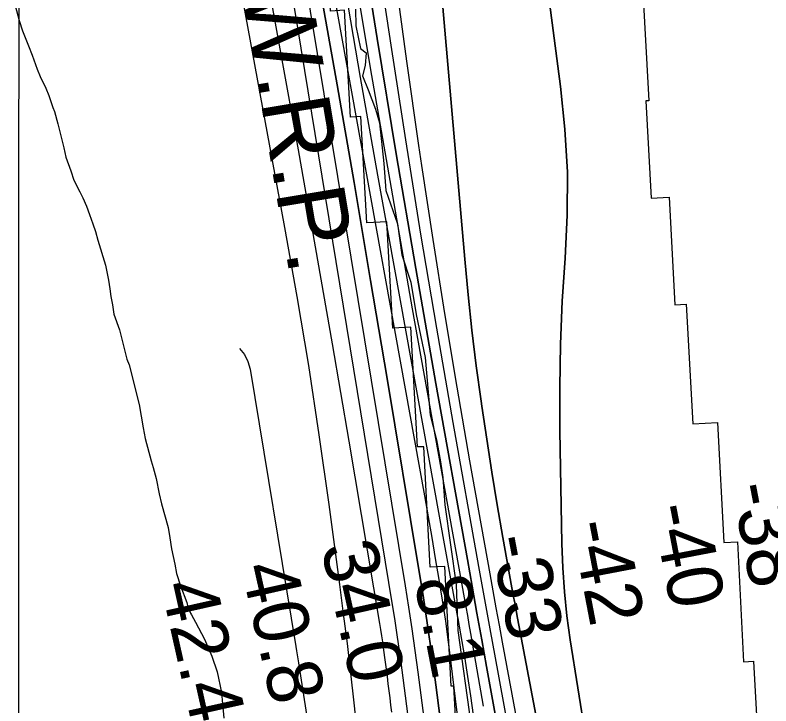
# Model space of a CAD drawing. Extents: x 3263578 to 3301413, y 764927 to 798602.
# Drawn here: x 3275589 to 3276507, y 791406 to 792245 of the extents above; entities that cross this region are included whole.
import ezdxf

# ---------------------------------------------------------------- set-up
doc = ezdxf.new("R2010")
doc.units = 0
for name, color, linetype in [('V-GRID-MAJR', 7, 'Continuous'), ('V-RIVR-EDGE', 7, 'Continuous'), ('V-RIVR-RANG', 7, 'Continuous'), ('V-RRAP-RVMT', 7, 'Continuous'), ('V-SITE-VEGE', 7, 'Continuous'), ('V-TOPO-DPTH', 7, 'Continuous'), ('V-TOPO-MAJR', 7, 'Continuous'), ('V-TOPO-MINR', 7, 'Continuous'), ('V-TOPO-WATR', 7, 'Continuous'), ('V-TOPO-WATR-IDEN', 7, 'Continuous')]:
    doc.layers.add(name, color=color, linetype=linetype)

msp = doc.modelspace()

# ---------------------------------------------------------------- linework, layer by layer
at = {"layer": 'V-GRID-MAJR'}
msp.add_spline([(3275591.3, 775830.01), (3275592.19, 781889.43), (3275593.07, 787951.47), (3275593.95, 794013.53), (3275593.95, 794016.1)], degree=3, dxfattribs=at)
at = {"layer": 'V-RIVR-EDGE'}
msp.add_lwpolyline([(3276002.53, 792252.02), (3276002.91, 792231.59), (3276008.49, 792204.19), (3276015.44, 792198.96), (3276014.09, 792183.74), (3276011.02, 792171.15), (3276017.93, 792154.18), (3276026.57, 792130.68), (3276031.31, 792114.15), (3276036.84, 792064.59), (3276039.36, 792031.98), (3276053.17, 791991.52), (3276058.73, 791953.69), (3276069.52, 791920.63), (3276075.94, 791881.06), (3276087.11, 791828.87), (3276093.02, 791758.87), (3276100.77, 791728.86), (3276105.49, 791702.33), (3276108.49, 791683.2), (3276111.01, 791650.15), (3276124.68, 791552.75), (3276126.72, 791497.54), (3276142.52, 791384.05)], dxfattribs=at)
at = {"layer": 'V-RRAP-RVMT'}
for points in [[(3276267.24, 792666.6), (3276274.68, 792537.22), (3276298.41, 792538.57), (3276305.94, 792408.68), (3276322.98, 792409.51), (3276330.56, 792279.44), (3276350.63, 792280.61), (3276358.29, 792140.86), (3276354.91, 792140.71), (3276361.31, 792022.46), (3276383.18, 792023.54), (3276389.99, 791893.13), (3276403.81, 791893.89), (3276411.76, 791748.26), (3276441.88, 791749.86), (3276449.37, 791604.37), (3276466.05, 791605.25), (3276473.51, 791459.54), (3276485.65, 791460.18), (3276493.76, 791314.12)], [(3276129.93, 791283.92), (3276121.78, 791429.9), (3276118.49, 791429.76), (3276110.85, 791575.36), (3276092.94, 791574.4), (3276085.31, 791720.67), (3276077.63, 791720.33), (3276069.68, 791865.87), (3276047.54, 791864.64), (3276040.6, 791993.84), (3276015.97, 791992.49), (3276008.76, 792121.61), (3275996.23, 792121.03), (3275988.92, 792250.72), (3275972.19, 792249.74), (3275964.1, 792388.74), (3275967.37, 792388.96), (3275964.86, 792431.92)]]:
    msp.add_lwpolyline(points, dxfattribs=at)
at = {"layer": 'V-SITE-VEGE'}
for p, q in [((3275589.1, 792256.42), (3275593.94, 792238.22)), ((3275593.94, 792238.22), (3275598.21, 792225.67)), ((3275598.21, 792225.67), (3275605.55, 792207.45)), ((3275605.55, 792207.45), (3275609.83, 792196.14)), ((3275609.83, 792196.14), (3275615.93, 792179.18)), ((3275615.93, 792179.18), (3275619.6, 792170.39)), ((3275619.6, 792170.39), (3275626.35, 792155.93)), ((3275626.35, 792155.93), (3275630.03, 792147.13)), ((3275630.03, 792147.13), (3275634.9, 792132.69)), ((3275634.9, 792132.69), (3275636.73, 792127.66)), ((3275636.73, 792127.66), (3275640.97, 792112.6)), ((3275640.97, 792112.6), (3275648.21, 792083.74)), ((3275648.21, 792083.74), (3275650.61, 792072.45)), ((3275650.61, 792072.45), (3275656.71, 792055.5)), ((3275656.71, 792055.5), (3275660.37, 792044.2)), ((3275660.37, 792044.2), (3275667.75, 792030.36)), ((3275667.75, 792030.36), (3275671.43, 792022.81)), ((3275671.43, 792022.81), (3275675.72, 792012.76)), ((3275675.72, 792012.76), (3275679.39, 792002.71)), ((3275679.39, 792002.71), (3275683.66, 791991.4)), ((3275683.66, 791991.4), (3275686.7, 791981.98)), ((3275686.7, 791981.98), (3275689.73, 791971.32)), ((3275689.73, 791971.32), (3275698.84, 791941.19)), ((3275698.84, 791941.19), (3275702.43, 791923)), ((3275702.43, 791923), (3275704.21, 791912.34)), ((3275704.21, 791912.34), (3275705.37, 791902.94)), ((3275705.37, 791902.94), (3275707.16, 791892.91)), ((3275707.16, 791892.91), (3275708.93, 791881.63)), ((3275708.93, 791881.63), (3275715.64, 791862.79)), ((3275715.64, 791862.79), (3275724.7, 791827.03)), ((3275724.7, 791827.03), (3275727.76, 791820.11)), ((3275727.76, 791820.11), (3275739.83, 791771.81)), ((3275739.83, 791771.81), (3275744.58, 791743.6)), ((3275744.58, 791743.6), (3275746.96, 791730.43)), ((3275746.96, 791730.43), (3275754.22, 791703.45)), ((3275754.22, 791703.45), (3275756.65, 791695.29)), ((3275756.65, 791695.29), (3275760.28, 791682.11)), ((3275760.28, 791682.11), (3275763.86, 791663.3)), ((3275763.86, 791663.3), (3275766.88, 791651.38)), ((3275766.88, 791651.38), (3275774.75, 791622.51)), ((3275774.75, 791622.51), (3275777.14, 791609.97)), ((3275777.14, 791609.97), (3275778.89, 791596.81)), ((3275778.89, 791596.81), (3275783.1, 791577.99)), ((3275783.1, 791577.99), (3275784.87, 791566.71)), ((3275784.87, 791566.71), (3275789.74, 791551.64)), ((3275789.74, 791551.64), (3275797.69, 791531.54)), ((3275797.69, 791531.54), (3275798.89, 791525.89)), ((3275798.89, 791525.89), (3275801.95, 791518.36)), ((3275801.95, 791518.36), (3275803.18, 791516.47)), ((3275803.18, 791516.47), (3275808.11, 791507.66)), ((3275808.11, 791507.66), (3275819.18, 791486.9)), ((3275819.18, 791486.9), (3275827.75, 791466.16)), ((3275827.75, 791466.16), (3275834.46, 791447.32)), ((3275834.46, 791447.32), (3275839.86, 791422.24)), ((3275839.86, 791422.24), (3275840.98, 791408.46)), ((3275840.98, 791408.46), (3275842.7, 791390.91))]:
    msp.add_line(p, q, dxfattribs=at)
at = {"layer": 'V-TOPO-DPTH'}
for points in [[(3275902.98, 793401.93), (3275983.68, 792824.87), (3275986.82, 792801.94), (3275989.88, 792778.99), (3275992.81, 792756.03), (3275995.65, 792733.06), (3276024.39, 792495.53), (3276037.16, 792393.17), (3276050.44, 792290.87), (3276064.48, 792188.68), (3276079.03, 792086.55), (3276082.61, 792062.1), (3276096.18, 791972.32), (3276110.32, 791882.63), (3276125.32, 791793.08), (3276140.88, 791703.63), (3276165.43, 791566.4), (3276169.16, 791545.63), (3276172.93, 791524.87), (3276176.73, 791504.11), (3276180.56, 791483.35), (3276271.79, 790991.22)], [(3275902.98, 793401.93), (3275983.68, 792824.87), (3275986.82, 792801.94), (3275989.88, 792778.99), (3275992.81, 792756.03), (3275995.65, 792733.06), (3276024.39, 792495.53), (3276037.16, 792393.17), (3276050.44, 792290.87), (3276064.48, 792188.68), (3276079.03, 792086.55), (3276082.61, 792062.1), (3276096.18, 791972.32), (3276110.32, 791882.63), (3276125.32, 791793.08), (3276140.88, 791703.63), (3276165.43, 791566.4), (3276169.16, 791545.63), (3276172.93, 791524.87), (3276176.73, 791504.11), (3276180.56, 791483.35), (3276271.79, 790991.22)], [(3276222.33, 792377.96), (3276251.34, 792158.16), (3276256.54, 792106.13), (3276259.55, 792054.05), (3276259.28, 792001.89), (3276256.81, 791949.66), (3276253.44, 791897.37), (3276251.09, 791845.05), (3276250.25, 791792.68), (3276250.42, 791740.28), (3276252.85, 791603.09), (3276253.99, 791573.71), (3276255.93, 791544.41), (3276259.09, 791515.21), (3276263.06, 791486.09), (3276281.45, 791369.4)], [(3276281.45, 791369.4), (3276263.06, 791486.09), (3276259.09, 791515.21), (3276255.93, 791544.41), (3276253.99, 791573.71), (3276252.85, 791603.09), (3276250.42, 791740.28), (3276250.25, 791792.68), (3276251.09, 791845.05), (3276253.44, 791897.37), (3276256.81, 791949.66), (3276259.28, 792001.89), (3276259.55, 792054.05), (3276256.54, 792106.13), (3276251.34, 792158.16), (3276222.33, 792377.96)], [(3276185.5, 791320.06), (3276161.51, 791453.66), (3276155.67, 791486.17), (3276149.84, 791518.68), (3276144.03, 791551.19), (3276138.22, 791583.71), (3276100.07, 791797.47), (3276075.64, 791936.94), (3276051.79, 792076.51), (3276028.82, 792216.22), (3276006.43, 792356.04)], [(3276185.5, 791320.06), (3276161.51, 791453.66), (3276155.67, 791486.17), (3276149.84, 791518.68), (3276144.03, 791551.19), (3276138.22, 791583.71), (3276100.07, 791797.47), (3276075.64, 791936.94), (3276051.79, 792076.51), (3276028.82, 792216.22), (3276006.43, 792356.04)], [(3276364.65, 790639.69), (3276199.09, 791512.63), (3276197.36, 791521.8), (3276195.66, 791530.97), (3276193.98, 791540.14), (3276192.31, 791549.32), (3276181.35, 791610.39), (3276174.43, 791650.14), (3276167.81, 791689.94), (3276161.61, 791729.81), (3276155.71, 791769.73), (3276154.83, 791775.88), (3276149.06, 791818.95), (3276143.75, 791862.07), (3276139.15, 791905.27), (3276135.01, 791948.53), (3276101.79, 792328.94)], [(3276364.65, 790639.69), (3276199.09, 791512.63), (3276197.36, 791521.8), (3276195.66, 791530.97), (3276193.98, 791540.14), (3276192.31, 791549.32), (3276181.35, 791610.39), (3276174.43, 791650.14), (3276167.81, 791689.94), (3276161.61, 791729.81), (3276155.71, 791769.73), (3276154.83, 791775.88), (3276149.06, 791818.95), (3276143.75, 791862.07), (3276139.15, 791905.27), (3276135.01, 791948.53), (3276101.79, 792328.94)], [(3275987.62, 792288.03), (3276008.2, 792169.18), (3276029.27, 792050.42), (3276124.69, 791522.06), (3276125.56, 791517.23), (3276126.41, 791512.4), (3276127.26, 791507.57), (3276128.09, 791502.73), (3276134.51, 791465.31), (3276138.38, 791441.74), (3276142.03, 791418.14), (3276145.35, 791394.49)], [(3275987.62, 792288.03), (3276008.2, 792169.18), (3276029.27, 792050.42), (3276124.69, 791522.06), (3276125.56, 791517.23), (3276126.41, 791512.4), (3276127.26, 791507.57), (3276128.09, 791502.73), (3276134.51, 791465.31), (3276138.38, 791441.74), (3276142.03, 791418.14), (3276145.35, 791394.49)], [(3276120.82, 791267.85), (3276099.86, 791431.53), (3276095.02, 791467.68), (3276089.91, 791503.8), (3276084.4, 791539.85), (3276078.61, 791575.87), (3276040.7, 791803.64), (3276020.73, 791922.52), (3276000.54, 792041.36), (3275980, 792160.14), (3275959.24, 792278.88)]]:
    msp.add_lwpolyline(points, dxfattribs=at)
at = {"layer": 'V-TOPO-MAJR'}
msp.add_lwpolyline([(3275818.67, 792709.87), (3275911.47, 792199.28), (3275932.67, 792081.39), (3275953.57, 791963.44), (3275974.03, 791845.42), (3275994.2, 791727.34), (3276031.58, 791505.93), (3276032.79, 791498.52), (3276033.95, 791491.09), (3276035.04, 791483.66), (3276036.07, 791476.22), (3276040.69, 791441.48), (3276041.81, 791432.83), (3276042.9, 791424.18), (3276043.94, 791415.52), (3276044.94, 791406.86), (3276045.89, 791398.19)], dxfattribs=at)
at = {"layer": 'V-TOPO-MINR'}
for points in [[(3275681.56, 794016.11), (3275683.11, 793996.55), (3275689.57, 793926.33), (3275697.34, 793856.24), (3275706, 793786.24), (3275717.41, 793700.57), (3275721.05, 793673.48), (3275724.73, 793646.39), (3275728.49, 793619.31), (3275732.28, 793592.24), (3275745.05, 793501.98), (3275755.18, 793429.77), (3275765.2, 793357.54), (3275775.06, 793285.29), (3275784.8, 793213.03), (3275846.6, 792750.5), (3276046.93, 791528.62), (3276049.59, 791511.93), (3276052.15, 791495.22), (3276054.56, 791478.49), (3276056.86, 791461.75), (3276067.26, 791383.59)], [(3275902.98, 793401.93), (3275983.68, 792824.87), (3275986.82, 792801.94), (3275989.88, 792778.99), (3275992.81, 792756.03), (3275995.65, 792733.06), (3276024.39, 792495.53), (3276037.16, 792393.17), (3276050.44, 792290.87), (3276064.48, 792188.68), (3276079.03, 792086.55), (3276082.61, 792062.1), (3276096.18, 791972.32), (3276110.32, 791882.63), (3276125.32, 791793.08), (3276140.88, 791703.63), (3276165.43, 791566.4), (3276169.16, 791545.63), (3276172.93, 791524.87), (3276176.73, 791504.11), (3276180.56, 791483.35), (3276271.79, 790991.22)], [(3275713.79, 793258.57), (3275716.76, 793192.59), (3275722.77, 793126.81), (3275730.82, 793061.18), (3275768.03, 792806.54), (3275773.26, 792772.09), (3275778.75, 792737.68), (3275784.61, 792703.34), (3275790.73, 792669.03), (3275916.31, 791987.01), (3275931.13, 791903.13), (3275945.12, 791819.12), (3275957.9, 791734.92), (3275969.85, 791650.58), (3275982.89, 791553.5), (3275987.57, 791517.59), (3275992.07, 791481.66), (3275996.28, 791445.69), (3276000.3, 791409.7), (3276016.15, 791262.77)], [(3275795.08, 793260.4), (3275808.17, 793162.82), (3275821.24, 793065.24), (3275854.74, 792814.52), (3275858.9, 792784.28), (3275863.2, 792754.06), (3275867.73, 792723.88), (3275872.4, 792693.71), (3275877.26, 792663.57), (3275882.2, 792633.45), (3275887.27, 792603.35), (3275892.42, 792573.26), (3275901.34, 792521.94), (3275910.95, 792466.19), (3275920.47, 792410.43), (3275929.85, 792354.64), (3275939.13, 792298.84), (3276062.5, 791551.8), (3276066.69, 791525.63), (3276070.7, 791499.43), (3276074.45, 791473.2), (3276078.03, 791446.93), (3276093.95, 791325.7)], [(3276013.79, 792416.38), (3276045.19, 792208.16), (3276062.96, 792093.5), (3276081.35, 791978.94), (3276100.66, 791864.54), (3276120.59, 791750.23), (3276151.88, 791575.03), (3276156.65, 791548.4), (3276161.44, 791521.79), (3276166.26, 791495.17), (3276171.11, 791468.56), (3276227.64, 791159.17)], [(3276222.33, 792377.96), (3276251.34, 792158.16), (3276256.54, 792106.13), (3276259.55, 792054.05), (3276259.28, 792001.89), (3276256.81, 791949.66), (3276253.44, 791897.37), (3276251.09, 791845.05), (3276250.25, 791792.68), (3276250.42, 791740.28), (3276252.85, 791603.09), (3276253.99, 791573.71), (3276255.93, 791544.41), (3276259.09, 791515.21), (3276263.06, 791486.09), (3276281.45, 791369.4)], [(3276006.43, 792356.04), (3276028.82, 792216.22), (3276051.79, 792076.51), (3276075.64, 791936.94), (3276100.07, 791797.47), (3276138.22, 791583.71), (3276144.03, 791551.19), (3276149.84, 791518.68), (3276155.67, 791486.17), (3276161.51, 791453.66), (3276185.5, 791320.06)], [(3276101.79, 792328.94), (3276135.01, 791948.53), (3276139.15, 791905.27), (3276143.75, 791862.07), (3276149.06, 791818.95), (3276154.83, 791775.88), (3276155.71, 791769.73), (3276161.61, 791729.81), (3276167.81, 791689.94), (3276174.43, 791650.14), (3276181.35, 791610.39), (3276192.31, 791549.32), (3276193.98, 791540.14), (3276195.66, 791530.97), (3276197.36, 791521.8), (3276199.09, 791512.63), (3276364.65, 790639.69)], [(3275996.04, 792327.45), (3276020.32, 792180.87), (3276045.51, 792034.44), (3276071.3, 791888.11), (3276134.3, 791537.18), (3276136.23, 791526.36), (3276138.16, 791515.55), (3276140.08, 791504.73), (3276141.99, 791493.91), (3276157.53, 791405.57)], [(3275969.26, 792309.16), (3275985.25, 792219), (3276085.94, 791660.95), (3276090.46, 791635.61), (3276094.91, 791610.26), (3276099.27, 791584.9), (3276103.57, 791559.52), (3276107.64, 791534.11), (3276111.48, 791508.67), (3276114.98, 791483.18), (3276118.25, 791457.65), (3276148.49, 791207.82)], [(3275959.24, 792278.88), (3275980, 792160.14), (3276000.54, 792041.36), (3276020.73, 791922.52), (3276040.7, 791803.64), (3276078.61, 791575.87), (3276084.4, 791539.85), (3276089.91, 791503.8), (3276095.02, 791467.68), (3276099.86, 791431.53), (3276120.82, 791267.85)], [(3275861.43, 791839.92), (3275867.6, 791832.71), (3275871.77, 791824.19), (3275874.61, 791814.78), (3275930.04, 791477.83), (3275930.84, 791472.88), (3275931.64, 791467.94), (3275932.42, 791462.99), (3275933.19, 791458.04), (3275938.04, 791426.52), (3275941.22, 791405.81), (3275944.37, 791385.1), (3275947.5, 791364.38), (3275950.62, 791343.66), (3275956.44, 791304.71), (3275961.55, 791264.45), (3275965.46, 791224.1), (3275967.56, 791183.61), (3275968.47, 791143.04), (3275968.48, 790958.46), (3275964.95, 790949.68), (3275959.79, 790943.97), (3275954.21, 790943.17)]]:
    msp.add_lwpolyline(points, dxfattribs=at)
at = {"layer": 'V-TOPO-WATR'}
msp.add_lwpolyline([(3275987.62, 792288.03), (3276008.2, 792169.18), (3276029.27, 792050.42), (3276124.69, 791522.06), (3276125.56, 791517.23), (3276126.41, 791512.4), (3276127.26, 791507.57), (3276128.09, 791502.73), (3276134.51, 791465.31), (3276138.38, 791441.74), (3276142.03, 791418.14), (3276145.35, 791394.49)], dxfattribs=at)

# ---------------------------------------------------------------- texts
at = {"layer": 'V-RIVR-RANG'}
for s, rotation, p in [('-38', 280.82614, (3276458.69, 791672.92)), ('-40', 280.82614, (3276361.8, 791647.49)), ('-42', 280.82614, (3276263.92, 791627.24)), ('34.0', 282.60833, (3275960.19, 791599.16)), ('-33', 280.82614, (3276165.59, 791609.32)), ('40.8', 282.60833, (3275863.29, 791574.26)), ('8.1', 280.82614, (3276073.55, 791558.5)), ('42.4', 282.60833, (3275765.75, 791552.2))]:
    msp.add_text(s, height=67, rotation=rotation, dxfattribs=at).set_placement(p)
at = {"layer": 'V-TOPO-WATR-IDEN'}
msp.add_text('L.W.R.P.', height=83, rotation=279.47661, dxfattribs=at).set_placement((3275849.51, 792365.34))

doc.saveas('drawing.dxf')
